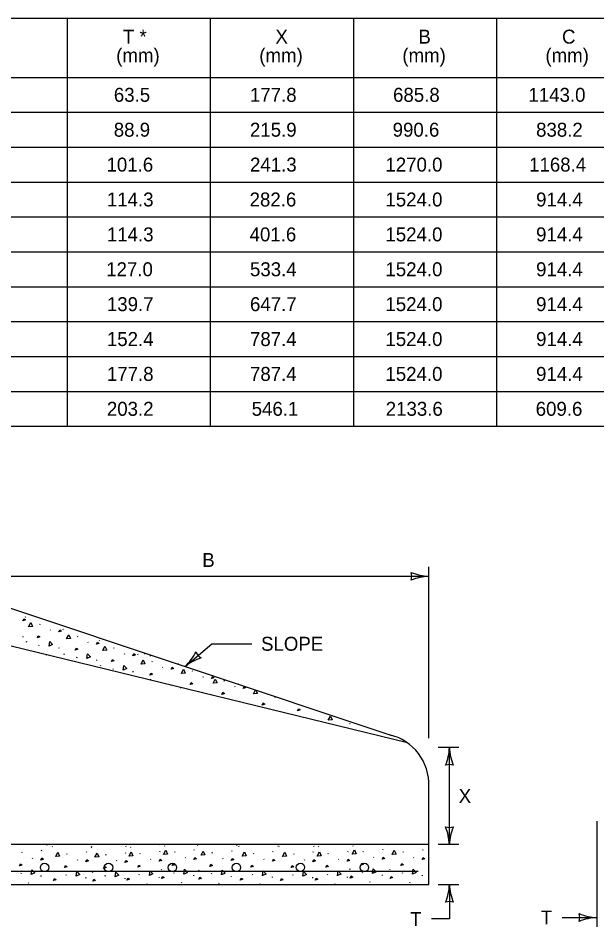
# Model space of a CAD drawing. Extents: x 49991.4 to 50021, y 49987.6 to 50011.4.
# Drawn here: x 50002.813 to 50005.302, y 50004.881 to 50008.788 of the extents above; entities that cross this region are included whole.
import ezdxf

# ---------------------------------------------------------------- set-up
doc = ezdxf.new("R2010")
doc.units = 0
for name, color, linetype in [('Level 1', 7, 'Continuous'), ('Level 2', 7, 'Continuous'), ('Level 3', 7, 'Continuous')]:
    doc.layers.add(name, color=color, linetype=linetype)

msp = doc.modelspace()

# ---------------------------------------------------------------- linework, layer by layer
at = {"layer": 'Level 1'}
for p, q in [((50002.6674, 50006.2887), (50004.4205, 50005.7044)), ((50002.8423, 50006.215), (50002.8437, 50006.2129)), ((50002.9058, 50006.1813), (50002.9073, 50006.1845)), ((50002.9502, 50006.1586), (50002.9517, 50006.1564)), ((50003.0051, 50006.1621), (50003.0065, 50006.16)), ((50002.6674, 50006.1169), (50004.481, 50005.6755)), ((50002.8326, 50006.1298), (50002.833, 50006.1266)), ((50002.8483, 50006.1056), (50002.8497, 50006.1088)), ((50003.0686, 50006.1284), (50003.0701, 50006.1316)), ((50003.0991, 50006.1453), (50003.0994, 50006.1434)), ((50003.1609, 50006.1127), (50003.1623, 50006.1106)), ((50002.9023, 50006.0911), (50002.9037, 50006.0943)), ((50002.9867, 50006.0822), (50002.9871, 50006.079)), ((50003.113, 50006.1057), (50003.1145, 50006.1035)), ((50003.2244, 50006.079), (50003.2259, 50006.0822)), ((50002.9346, 50006.0499), (50002.936, 50006.0531)), ((50003.0111, 50006.0527), (50003.0125, 50006.0559)), ((50003.0651, 50006.0382), (50003.0665, 50006.0414)), ((50003.2688, 50006.0563), (50003.2703, 50006.0541)), ((50003.3256, 50006.0545), (50003.327, 50006.0524)), ((50003.3563, 50006.0556), (50003.3566, 50006.0537)), ((50003.3801, 50006.0473), (50003.3804, 50006.0454)), ((50003.1495, 50006.0293), (50003.1499, 50006.0261)), ((50003.1669, 50006.0033), (50003.1683, 50006.0065)), ((50003.2209, 50005.9888), (50003.2223, 50005.992)), ((50003.3891, 50006.0208), (50003.3906, 50006.024)), ((50003.4335, 50005.9981), (50003.435, 50005.9959)), ((50003.4991, 50006.0139), (50003.5005, 50006.0118)), ((50003.3053, 50005.9799), (50003.3057, 50005.9767)), ((50003.5626, 50005.9802), (50003.5641, 50005.9834)), ((50003.607, 50005.9575), (50003.6085, 50005.9553)), ((50003.6366, 50005.965), (50003.6369, 50005.9631)), ((50003.3816, 50005.944), (50003.3836, 50005.9457)), ((50003.47, 50005.9217), (50003.4704, 50005.9185)), ((50003.6989, 50005.9379), (50003.7004, 50005.9411)), ((50003.7433, 50005.9152), (50003.7448, 50005.913)), ((50003.7596, 50005.9265), (50003.7599, 50005.9246)), ((50003.5116, 50005.909), (50003.5136, 50005.9107)), ((50003.606, 50005.8887), (50003.608, 50005.8905)), ((50003.6435, 50005.8811), (50003.6439, 50005.8779)), ((50003.9168, 50005.8694), (50003.9183, 50005.8672)), ((50004.2382, 50005.7564), (50004.2397, 50005.7542)), ((50004.5792, 50005.2351), (50004.5792, 50005.5071)), ((50004.5792, 50005.2351), (50001.2456, 50005.2351)), ((50002.9133, 50005.2086), (50002.9148, 50005.2118)), ((50002.9343, 50005.2349), (50002.9357, 50005.2328)), ((50002.9586, 50005.227), (50002.96, 50005.2249)), ((50003.1269, 50005.2235), (50003.1283, 50005.2214)), ((50003.1273, 50005.2278), (50003.1287, 50005.2257)), ((50003.2739, 50005.2288), (50003.2753, 50005.2267)), ((50003.2956, 50005.2243), (50003.297, 50005.2222)), ((50003.4226, 50005.2358), (50003.424, 50005.2337)), ((50003.4426, 50005.2296), (50003.444, 50005.2275)), ((50003.5703, 50005.2103), (50003.5718, 50005.2135)), ((50003.5837, 50005.2323), (50003.5851, 50005.2302)), ((50003.5913, 50005.2366), (50003.5927, 50005.2345)), ((50003.7314, 50005.2068), (50003.7329, 50005.21)), ((50003.7524, 50005.2331), (50003.7538, 50005.231)), ((50003.7608, 50005.2287), (50003.7622, 50005.2266)), ((50003.9295, 50005.2295), (50003.9309, 50005.2274)), ((50003.9344, 50005.227), (50003.9358, 50005.2249)), ((50004.0831, 50005.2287), (50004.0845, 50005.2266)), ((50004.1031, 50005.2278), (50004.1045, 50005.2257)), ((50004.2518, 50005.2295), (50004.2532, 50005.2274)), ((50004.3814, 50005.2121), (50004.3829, 50005.2153)), ((50004.4054, 50005.2358), (50004.4068, 50005.2337)), ((50004.5531, 50005.2103), (50004.5546, 50005.2135)), ((50004.5741, 50005.2366), (50004.5755, 50005.2345)), ((50004.5792, 50005.0634), (50004.5792, 50005.2351)), ((50002.8291, 50005.2004), (50002.8306, 50005.2036)), ((50002.8735, 50005.1777), (50002.875, 50005.1755)), ((50003.0221, 50005.1933), (50003.0236, 50005.1965)), ((50003.1063, 50005.2015), (50003.1078, 50005.2047)), ((50003.1904, 50005.1898), (50003.1919, 50005.193)), ((50003.2746, 50005.198), (50003.2761, 50005.2012)), ((50003.3374, 50005.1951), (50003.3389, 50005.1983)), ((50003.3818, 50005.1724), (50003.3833, 50005.1702)), ((50003.4216, 50005.2033), (50003.4231, 50005.2065)), ((50003.4861, 50005.2021), (50003.4876, 50005.2053)), ((50003.5305, 50005.1794), (50003.532, 50005.1772)), ((50003.6472, 50005.1986), (50003.6487, 50005.2018)), ((50003.6916, 50005.1759), (50003.6931, 50005.1737)), ((50003.8243, 50005.195), (50003.8258, 50005.1982)), ((50003.8687, 50005.1723), (50003.8702, 50005.1701)), ((50003.9085, 50005.2032), (50003.91, 50005.2064)), ((50003.9979, 50005.1933), (50003.9994, 50005.1965)), ((50004.0821, 50005.2015), (50004.0836, 50005.2047)), ((50004.1466, 50005.195), (50004.1481, 50005.1982)), ((50004.191, 50005.1723), (50004.1925, 50005.1701)), ((50004.2308, 50005.2032), (50004.2323, 50005.2064)), ((50004.2972, 50005.2039), (50004.2987, 50005.2071)), ((50004.3416, 50005.1812), (50004.3431, 50005.179)), ((50004.4689, 50005.2021), (50004.4704, 50005.2053)), ((50004.5133, 50005.1794), (50004.5148, 50005.1772)), ((50003.0665, 50005.1706), (50003.068, 50005.1684)), ((50003.2348, 50005.1671), (50003.2363, 50005.1649)), ((50004.0423, 50005.1706), (50004.0438, 50005.1684)), ((50002.8256, 50005.1102), (50002.827, 50005.1134)), ((50002.91, 50005.1013), (50002.9104, 50005.0981)), ((50002.9646, 50005.1176), (50002.966, 50005.1208)), ((50003.0186, 50005.1031), (50003.02, 50005.1063)), ((50003.103, 50005.0942), (50003.1034, 50005.091)), ((50003.1329, 50005.1141), (50003.1343, 50005.1173)), ((50003.1869, 50005.0996), (50003.1883, 50005.1028)), ((50003.2799, 50005.1194), (50003.2813, 50005.1226)), ((50003.3339, 50005.1049), (50003.3353, 50005.1081)), ((50003.4183, 50005.096), (50003.4187, 50005.0928)), ((50003.4286, 50005.1264), (50003.43, 50005.1296)), ((50003.4826, 50005.1119), (50003.484, 50005.1151)), ((50003.567, 50005.103), (50003.5674, 50005.0998)), ((50003.5897, 50005.1229), (50003.5911, 50005.1261)), ((50003.6437, 50005.1084), (50003.6451, 50005.1116)), ((50003.7281, 50005.0995), (50003.7285, 50005.0963)), ((50003.7668, 50005.1193), (50003.7682, 50005.1225)), ((50003.8208, 50005.1048), (50003.8222, 50005.108)), ((50003.9052, 50005.0959), (50003.9056, 50005.0927)), ((50003.9404, 50005.1176), (50003.9418, 50005.1208)), ((50003.9944, 50005.1031), (50003.9958, 50005.1063)), ((50004.0788, 50005.0942), (50004.0792, 50005.091)), ((50004.0891, 50005.1193), (50004.0905, 50005.1225)), ((50004.1431, 50005.1048), (50004.1445, 50005.108)), ((50004.2275, 50005.0959), (50004.2279, 50005.0927)), ((50004.2397, 50005.1282), (50004.2411, 50005.1314)), ((50004.2937, 50005.1137), (50004.2951, 50005.1169)), ((50004.3781, 50005.1048), (50004.3785, 50005.1016)), ((50004.4114, 50005.1264), (50004.4128, 50005.1296)), ((50004.4654, 50005.1119), (50004.4668, 50005.1151)), ((50004.5498, 50005.103), (50004.5502, 50005.0998)), ((50001.0497, 50005.0634), (50004.5792, 50005.0634)), ((50002.8579, 50005.069), (50002.8593, 50005.0722)), ((50003.0509, 50005.0619), (50003.0523, 50005.0651)), ((50003.2713, 50005.0907), (50003.2717, 50005.0875)), ((50003.3662, 50005.0637), (50003.3676, 50005.0669)), ((50003.5149, 50005.0707), (50003.5163, 50005.0739)), ((50003.676, 50005.0672), (50003.6774, 50005.0704)), ((50003.8531, 50005.0636), (50003.8545, 50005.0668)), ((50004.0267, 50005.0619), (50004.0281, 50005.0651)), ((50004.1754, 50005.0636), (50004.1768, 50005.0668)), ((50004.326, 50005.0725), (50004.3274, 50005.0757)), ((50004.4977, 50005.0707), (50004.4991, 50005.0739))]:
    msp.add_line(p, q, dxfattribs=at)
for points in [[(50002.8334, 50006.1969), (50002.8377, 50006.2058), (50002.8448, 50006.2005), (50002.8334, 50006.1969)], [(50002.8579, 50006.1717), (50002.8675, 50006.1898), (50002.8749, 50006.1731), (50002.8582, 50006.1717)], [(50002.9875, 50006.1493), (50002.9918, 50006.1582), (50002.9989, 50006.1529), (50002.9875, 50006.1493)], [(50002.8953, 50006.1239), (50002.8995, 50006.1328), (50002.9066, 50006.1275), (50002.8953, 50006.1239)], [(50003.0207, 50006.1188), (50003.0303, 50006.1369), (50003.0377, 50006.1202), (50003.021, 50006.1188)], [(50002.9455, 50006.0874), (50002.9483, 50006.1077), (50002.961, 50006.0946), (50002.9458, 50006.0875)], [(50003.0581, 50006.071), (50003.0623, 50006.0799), (50003.0694, 50006.0746), (50003.0581, 50006.071)], [(50003.1503, 50006.0964), (50003.1546, 50006.1053), (50003.1617, 50006.1), (50003.1503, 50006.0964)], [(50003.1765, 50006.0694), (50003.1861, 50006.0875), (50003.1935, 50006.0708), (50003.1768, 50006.0694)], [(50003.1083, 50006.0345), (50003.1111, 50006.0548), (50003.1238, 50006.0417), (50003.1086, 50006.0346)], [(50003.2139, 50006.0216), (50003.2181, 50006.0305), (50003.2252, 50006.0252), (50003.2139, 50006.0216)], [(50003.3061, 50006.047), (50003.3104, 50006.0559), (50003.3175, 50006.0506), (50003.3061, 50006.047)], [(50003.2641, 50005.9851), (50003.2669, 50006.0054), (50003.2796, 50005.9923), (50003.2644, 50005.9852)], [(50003.3412, 50006.0112), (50003.3508, 50006.0293), (50003.3582, 50006.0126), (50003.3416, 50006.0112)], [(50003.4708, 50005.9888), (50003.4751, 50005.9977), (50003.4822, 50005.9924), (50003.4708, 50005.9888)], [(50003.3786, 50005.9634), (50003.3828, 50005.9723), (50003.3899, 50005.967), (50003.3786, 50005.9634)], [(50003.5147, 50005.9706), (50003.5243, 50005.9887), (50003.5317, 50005.972), (50003.515, 50005.9706)], [(50003.6443, 50005.9482), (50003.6486, 50005.9571), (50003.6557, 50005.9518), (50003.6443, 50005.9482)], [(50003.5521, 50005.9228), (50003.5563, 50005.9317), (50003.5634, 50005.9264), (50003.5521, 50005.9228)], [(50003.651, 50005.9283), (50003.6606, 50005.9464), (50003.668, 50005.9297), (50003.6514, 50005.9283)], [(50003.7806, 50005.9059), (50003.7849, 50005.9148), (50003.792, 50005.9095), (50003.7806, 50005.9059)], [(50003.6884, 50005.8805), (50003.6926, 50005.8894), (50003.6997, 50005.8841), (50003.6884, 50005.8805)], [(50003.8245, 50005.8825), (50003.8341, 50005.9006), (50003.8415, 50005.8839), (50003.8248, 50005.8825)], [(50003.8619, 50005.8347), (50003.8661, 50005.8436), (50003.8732, 50005.8383), (50003.8619, 50005.8347)], [(50004.0142, 50005.81), (50004.0184, 50005.8189), (50004.0255, 50005.8136), (50004.0142, 50005.81)], [(50004.1459, 50005.7695), (50004.1555, 50005.7876), (50004.1629, 50005.7709), (50004.1462, 50005.7695)], [(50003.4382, 50005.1925), (50003.4478, 50005.2106), (50003.4552, 50005.1939), (50003.4386, 50005.1925)], [(50004.2493, 50005.1943), (50004.2589, 50005.2124), (50004.2663, 50005.1957), (50004.2496, 50005.1943)], [(50004.421, 50005.1925), (50004.4306, 50005.2106), (50004.438, 50005.1939), (50004.4214, 50005.1925)], [(50002.9108, 50005.1684), (50002.9151, 50005.1773), (50002.9222, 50005.172), (50002.9108, 50005.1684)], [(50002.9742, 50005.1837), (50002.9838, 50005.2018), (50002.9912, 50005.1851), (50002.9746, 50005.1837)], [(50003.1425, 50005.1802), (50003.1521, 50005.1983), (50003.1595, 50005.1816), (50003.1428, 50005.1802)], [(50003.2895, 50005.1855), (50003.2991, 50005.2036), (50003.3065, 50005.1869), (50003.2898, 50005.1855)], [(50003.4191, 50005.1631), (50003.4234, 50005.172), (50003.4305, 50005.1667), (50003.4191, 50005.1631)], [(50003.5678, 50005.1701), (50003.5721, 50005.179), (50003.5792, 50005.1737), (50003.5678, 50005.1701)], [(50003.5993, 50005.189), (50003.6089, 50005.2071), (50003.6163, 50005.1904), (50003.5996, 50005.189)], [(50003.7289, 50005.1666), (50003.7332, 50005.1755), (50003.7403, 50005.1702), (50003.7289, 50005.1666)], [(50003.7764, 50005.1854), (50003.786, 50005.2035), (50003.7934, 50005.1868), (50003.7768, 50005.1854)], [(50003.906, 50005.163), (50003.9103, 50005.1719), (50003.9174, 50005.1666), (50003.906, 50005.163)], [(50003.95, 50005.1837), (50003.9596, 50005.2018), (50003.967, 50005.1851), (50003.9504, 50005.1837)], [(50004.0987, 50005.1854), (50004.1083, 50005.2035), (50004.1157, 50005.1868), (50004.099, 50005.1854)], [(50004.2283, 50005.163), (50004.2326, 50005.1719), (50004.2397, 50005.1666), (50004.2283, 50005.163)], [(50004.3789, 50005.1719), (50004.3832, 50005.1808), (50004.3903, 50005.1755), (50004.3789, 50005.1719)], [(50004.5506, 50005.1701), (50004.5549, 50005.179), (50004.562, 50005.1737), (50004.5506, 50005.1701)], [(50002.8186, 50005.143), (50002.8228, 50005.1519), (50002.8299, 50005.1466), (50002.8186, 50005.143)], [(50003.0116, 50005.1359), (50003.0158, 50005.1448), (50003.0229, 50005.1395), (50003.0116, 50005.1359)], [(50003.1038, 50005.1613), (50003.1081, 50005.1702), (50003.1152, 50005.1649), (50003.1038, 50005.1613)], [(50003.1799, 50005.1324), (50003.1841, 50005.1413), (50003.1912, 50005.136), (50003.1799, 50005.1324)], [(50003.2721, 50005.1578), (50003.2764, 50005.1667), (50003.2835, 50005.1614), (50003.2721, 50005.1578)], [(50003.3269, 50005.1377), (50003.3311, 50005.1466), (50003.3382, 50005.1413), (50003.3269, 50005.1377)], [(50003.4756, 50005.1447), (50003.4798, 50005.1536), (50003.4869, 50005.1483), (50003.4756, 50005.1447)], [(50003.6367, 50005.1412), (50003.6409, 50005.1501), (50003.648, 50005.1448), (50003.6367, 50005.1412)], [(50003.8138, 50005.1376), (50003.818, 50005.1465), (50003.8251, 50005.1412), (50003.8138, 50005.1376)], [(50003.9874, 50005.1359), (50003.9916, 50005.1448), (50003.9987, 50005.1395), (50003.9874, 50005.1359)], [(50004.0796, 50005.1613), (50004.0839, 50005.1702), (50004.091, 50005.1649), (50004.0796, 50005.1613)], [(50004.1361, 50005.1376), (50004.1403, 50005.1465), (50004.1474, 50005.1412), (50004.1361, 50005.1376)], [(50004.2867, 50005.1465), (50004.2909, 50005.1554), (50004.298, 50005.1501), (50004.2867, 50005.1465)], [(50004.4584, 50005.1447), (50004.4626, 50005.1536), (50004.4697, 50005.1483), (50004.4584, 50005.1447)], [(50004.5336, 50005.1185), (50002.5522, 50005.1185)], [(50002.8688, 50005.1065), (50002.8716, 50005.1268), (50002.8843, 50005.1137), (50002.8691, 50005.1066)], [(50003.0618, 50005.0994), (50003.0646, 50005.1197), (50003.0773, 50005.1066), (50003.0621, 50005.0995)], [(50003.2301, 50005.0959), (50003.2329, 50005.1162), (50003.2456, 50005.1031), (50003.2304, 50005.096)], [(50003.3771, 50005.1012), (50003.3799, 50005.1215), (50003.3926, 50005.1084), (50003.3774, 50005.1013)], [(50003.4293, 50005.0891), (50003.4336, 50005.098), (50003.4407, 50005.0927), (50003.4293, 50005.0891)], [(50003.5258, 50005.1082), (50003.5286, 50005.1285), (50003.5413, 50005.1154), (50003.5261, 50005.1083)], [(50003.5904, 50005.0856), (50003.5947, 50005.0945), (50003.6018, 50005.0892), (50003.5904, 50005.0856)], [(50003.6869, 50005.1047), (50003.6897, 50005.125), (50003.7024, 50005.1119), (50003.6872, 50005.1048)], [(50003.864, 50005.1011), (50003.8668, 50005.1214), (50003.8795, 50005.1083), (50003.8643, 50005.1012)], [(50004.0376, 50005.0994), (50004.0404, 50005.1197), (50004.0531, 50005.1066), (50004.0379, 50005.0995)], [(50004.1863, 50005.1011), (50004.1891, 50005.1214), (50004.2018, 50005.1083), (50004.1866, 50005.1012)], [(50004.2404, 50005.0909), (50004.2447, 50005.0998), (50004.2518, 50005.0945), (50004.2404, 50005.0909)], [(50004.3369, 50005.11), (50004.3397, 50005.1303), (50004.3524, 50005.1172), (50004.3372, 50005.1101)], [(50004.4121, 50005.0891), (50004.4164, 50005.098), (50004.4235, 50005.0927), (50004.4121, 50005.0891)], [(50004.5086, 50005.1082), (50004.5114, 50005.1285), (50004.5241, 50005.1154), (50004.5089, 50005.1083)], [(50002.9653, 50005.0803), (50002.9696, 50005.0892), (50002.9767, 50005.0839), (50002.9653, 50005.0803)], [(50003.1336, 50005.0768), (50003.1379, 50005.0857), (50003.145, 50005.0804), (50003.1336, 50005.0768)], [(50003.2806, 50005.0821), (50003.2849, 50005.091), (50003.292, 50005.0857), (50003.2806, 50005.0821)], [(50003.7675, 50005.082), (50003.7718, 50005.0909), (50003.7789, 50005.0856), (50003.7675, 50005.082)], [(50003.9411, 50005.0803), (50003.9454, 50005.0892), (50003.9525, 50005.0839), (50003.9411, 50005.0803)], [(50004.0898, 50005.082), (50004.0941, 50005.0909), (50004.1012, 50005.0856), (50004.0898, 50005.082)]]:
    msp.add_lwpolyline(points, dxfattribs=at)
for centre in [(50002.9262, 50005.1367), (50003.2014, 50005.1366), (50003.4762, 50005.1366), (50003.7517, 50005.1366), (50004.0268, 50005.1369), (50004.3019, 50005.1368)]:
    msp.add_circle(centre, 0.018, dxfattribs=at)
msp.add_arc((50004.358, 50005.4919), 0.2214, 358.1129, 76.3076, dxfattribs=at)
at = {"layer": 'Level 2'}
for p, q in [((50001.1776, 50008.788), (50007.9467, 50008.788)), ((50003.0236, 50008.788), (50003.0236, 50007.0334)), ((50003.639, 50008.788), (50003.639, 50007.0334)), ((50004.2544, 50008.788), (50004.2544, 50007.0334)), ((50004.8698, 50008.788), (50004.8698, 50007.0334)), ((50001.1776, 50008.5334), (50007.9467, 50008.5334)), ((50001.1776, 50008.3834), (50007.9467, 50008.3834)), ((50001.1776, 50008.2334), (50007.9467, 50008.2334)), ((50001.1776, 50008.0834), (50007.9467, 50008.0834)), ((50001.1776, 50007.9334), (50007.9467, 50007.9334)), ((50001.1776, 50007.7834), (50007.9467, 50007.7834)), ((50001.1776, 50007.6334), (50007.9467, 50007.6334)), ((50001.1776, 50007.4834), (50007.9467, 50007.4834)), ((50001.1776, 50007.3334), (50007.9467, 50007.3334)), ((50001.1776, 50007.1834), (50007.9467, 50007.1834)), ((50001.1776, 50007.0334), (50007.9467, 50007.0334))]:
    msp.add_line(p, q, dxfattribs=at)
at = {"layer": 'Level 3'}
for p, q in [((50004.5792, 50005.6919), (50004.5792, 50006.4284)), ((50002.6674, 50006.3884), (50004.5792, 50006.3884)), ((50003.5308, 50006.0009), (50003.6457, 50006.0981)), ((50003.6457, 50006.0981), (50003.8174, 50006.0981)), ((50004.7076, 50005.6519), (50004.6192, 50005.6519)), ((50004.6676, 50005.2351), (50004.6676, 50005.6519)), ((50005.3017, 50005.335), (50005.3017, 50004.8812)), ((50004.7076, 50005.2351), (50004.6192, 50005.2351)), ((50004.6192, 50005.0634), (50004.7076, 50005.0634)), ((50004.6676, 50005.0634), (50004.6676, 50004.915)), ((50004.6676, 50004.915), (50004.5907, 50004.915)), ((50005.1527, 50004.9212), (50005.3017, 50004.9212))]:
    msp.add_line(p, q, dxfattribs=at)
for centre, radius, start, end in [((50004.5884, 50006.6105), 0.2223, 247.456, 267.6395), ((50004.451, 50006.3884), 0.0548, 342.1388, 17.8612), ((50004.5907, 50006.1557), 0.233, 92.8273, 112.0772), ((50003.3717, 50006.1712), 0.233, 313.0571, 332.307), ((50003.6673, 50005.8254), 0.2223, 107.6858, 127.8694), ((50003.6287, 50006.0837), 0.0548, 202.3687, 238.091), ((50004.4455, 50005.661), 0.2223, 337.456, 357.6395), ((50004.9003, 50005.6634), 0.233, 182.8273, 202.0772), ((50004.6676, 50005.5237), 0.0548, 72.1388, 107.8612), ((50004.6676, 50005.3633), 0.0548, 252.1388, 287.8612), ((50004.4349, 50005.2236), 0.233, 2.8273, 22.0772), ((50004.8898, 50005.2259), 0.2223, 157.456, 177.6395), ((50004.4455, 50005.0725), 0.2223, 337.456, 357.6395), ((50004.9003, 50005.0749), 0.233, 182.8273, 202.0772), ((50004.6676, 50004.9352), 0.0548, 72.1388, 107.8612), ((50005.3108, 50005.1433), 0.2223, 247.456, 267.6395), ((50005.1735, 50004.9212), 0.0548, 342.1388, 17.8612), ((50005.3132, 50004.6885), 0.233, 92.8273, 112.0772)]:
    msp.add_arc(centre, radius, start, end, dxfattribs=at)

# ---------------------------------------------------------------- texts
at = {"layer": 'Level 2'}
for s, p in [('T *', (50003.2631, 50008.6786)), ('X', (50003.9193, 50008.6786)), ('B', (50004.5343, 50008.6786)), ('C', (50005.1519, 50008.6786)), ('(mm)', (50003.2344, 50008.5982)), ('(mm)', (50003.8498, 50008.5982)), ('(mm)', (50004.4651, 50008.5982)), ('(mm)', (50005.0805, 50008.5982)), ('63.5', (50003.2243, 50008.4284)), ('177.8', (50003.8098, 50008.4284)), ('685.8', (50004.4251, 50008.4284)), ('1143.0', (50005.0074, 50008.4284)), ('88.9', (50003.224, 50008.2784)), ('215.9', (50003.8097, 50008.2784)), ('990.6', (50004.4235, 50008.2784)), ('838.2', (50005.0404, 50008.2784)), ('101.6', (50003.1927, 50008.1284)), ('241.3', (50003.8099, 50008.1284)), ('1270.0', (50004.3923, 50008.1284)), ('1168.4', (50005.0104, 50008.1284)), ('114.3', (50003.1943, 50007.9784)), ('282.6', (50003.8082, 50007.9784)), ('1524.0', (50004.3923, 50007.9784)), ('914.4', (50005.0404, 50007.9784)), ('114.3', (50003.1944, 50007.8284)), ('401.6', (50003.8082, 50007.8284)), ('1524.0', (50004.3923, 50007.8284)), ('914.4', (50005.0404, 50007.8284)), ('127.0', (50003.1914, 50007.6784)), ('533.4', (50003.8098, 50007.6784)), ('1524.0', (50004.3923, 50007.6784)), ('914.4', (50005.0404, 50007.6784)), ('139.7', (50003.1944, 50007.5284)), ('647.7', (50003.8099, 50007.5284)), ('1524.0', (50004.3923, 50007.5284)), ('914.4', (50005.0404, 50007.5284)), ('152.4', (50003.1944, 50007.3784)), ('787.4', (50003.8098, 50007.3784)), ('1524.0', (50004.3923, 50007.3784)), ('914.4', (50005.0404, 50007.3784)), ('177.8', (50003.1944, 50007.2284)), ('787.4', (50003.8098, 50007.2284)), ('1524.0', (50004.3923, 50007.2284)), ('914.4', (50005.0403, 50007.2284)), ('203.2', (50003.1944, 50007.0784)), ('546.1', (50003.8171, 50007.0784)), ('2133.6', (50004.3937, 50007.0784)), ('609.6', (50005.0387, 50007.0784)), ('B', (50003.6046, 50006.4284)), ('SLOPE', (50003.8574, 50006.0681)), ('X', (50004.7076, 50005.4135)), ('T', (50004.4987, 50004.885)), ('T', (50005.0606, 50004.8912))]:
    msp.add_text(s, height=0.06, dxfattribs=at).set_placement(p)

doc.saveas('drawing.dxf')
